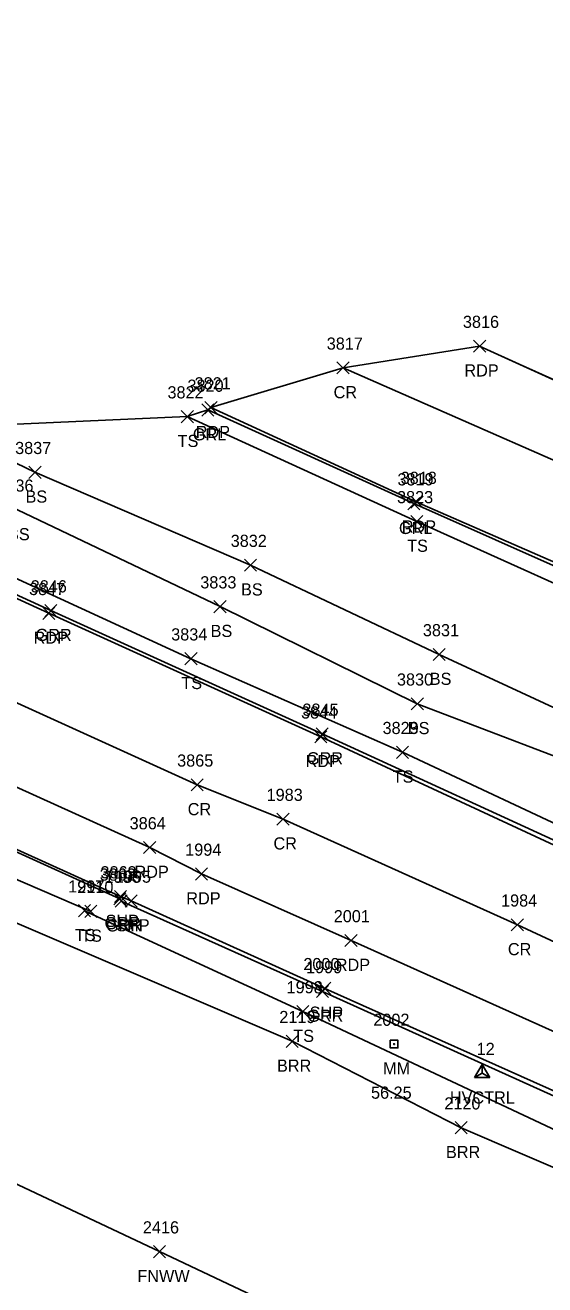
# Model space of a CAD drawing. Extents: x 1599569 to 1610055, y 642560 to 647860.
# Drawn here: x 1601302.9 to 1601388.5, y 647279.1 to 647486.4 of the extents above; entities that cross this region are included whole.
import ezdxf

# ---------------------------------------------------------------- set-up
doc = ezdxf.new("R2010")
doc.units = 0
for name, color, linetype in [('C_A', 7, 'Continuous'), ('C_I', 7, 'Continuous'), ('CPSM', 7, 'Continuous'), ('L_A', 7, 'Continuous'), ('L_I', 7, 'Continuous'), ('L_TIC', 7, 'Continuous'), ('LABL', 7, 'Continuous'), ('LELB', 7, 'Continuous'), ('LFNC', 7, 'Continuous'), ('LSOGP', 7, 'Continuous'), ('P_A', 7, 'Continuous'), ('P_I', 7, 'Continuous'), ('P_TIC', 7, 'Continuous'), ('PET', 7, 'Continuous'), ('PRC', 7, 'Continuous'), ('PSP', 7, 'Continuous'), ('R_A', 7, 'Continuous'), ('R_I', 7, 'Continuous'), ('R_TIC', 7, 'Continuous'), ('RGR', 7, 'Continuous'), ('S_A', 7, 'Continuous'), ('S_C', 7, 'Continuous'), ('S_I', 7, 'Continuous'), ('SRM', 7, 'Continuous')]:
    doc.layers.add(name, color=color, linetype=linetype)

msp = doc.modelspace()

# ---------------------------------------------------------------- linework, layer by layer
at = {"layer": 'CPSM'}
for p, q in [((1601376.92, 647313.16), (1601378.17, 647315.33)), ((1601379.42, 647313.16), (1601378.17, 647315.33)), ((1601378.17, 647313.88), (1601378.17, 647315.33)), ((1601376.92, 647313.16), (1601378.17, 647313.88)), ((1601376.92, 647313.16), (1601379.42, 647313.16)), ((1601378.17, 647313.88), (1601378.17, 647313.88)), ((1601378.17, 647313.88), (1601379.42, 647313.16))]:
    msp.add_line(p, q, dxfattribs=at)
at = {"layer": 'L_TIC'}
for points in [[(1601328.63, 647420.95), (1601330.63, 647422.95)], [(1601330.63, 647420.95), (1601328.63, 647422.95)], [(1601303.55, 647411.79), (1601305.55, 647413.79)], [(1601305.55, 647411.79), (1601303.55, 647413.79)], [(1601366.42, 647403.7), (1601368.42, 647405.7)], [(1601368.42, 647403.7), (1601366.42, 647405.7)], [(1601339.04, 647396.51), (1601341.04, 647398.51)], [(1601341.04, 647396.51), (1601339.04, 647398.51)], [(1601334.03, 647389.68), (1601336.03, 647391.68)], [(1601336.03, 647389.68), (1601334.03, 647391.68)], [(1601370.11, 647381.8), (1601372.11, 647383.8)], [(1601372.11, 647381.8), (1601370.11, 647383.8)], [(1601329.24, 647381.11), (1601331.24, 647383.11)], [(1601331.24, 647381.11), (1601329.24, 647383.11)], [(1601366.5, 647373.69), (1601368.5, 647375.69)], [(1601368.5, 647373.69), (1601366.5, 647375.69)], [(1601364.05, 647365.71), (1601366.05, 647367.71)], [(1601366.05, 647365.71), (1601364.05, 647367.71)], [(1601311.72, 647339.63), (1601313.72, 647341.63)], [(1601313.72, 647339.63), (1601311.72, 647341.63)], [(1601312.74, 647339.53), (1601314.74, 647341.53)], [(1601314.74, 647339.53), (1601312.74, 647341.53)], [(1601347.67, 647323.04), (1601349.67, 647325.04)], [(1601349.67, 647323.04), (1601347.67, 647325.04)], [(1601345.91, 647318.14), (1601347.91, 647320.14)], [(1601347.91, 647318.14), (1601345.91, 647320.14)], [(1601373.73, 647303.92), (1601375.73, 647305.92)], [(1601375.73, 647303.92), (1601373.73, 647305.92)], [(1601324.07, 647283.52), (1601326.07, 647285.52)], [(1601326.07, 647283.52), (1601324.07, 647285.52)]]:
    msp.add_lwpolyline(points, dxfattribs=at)
at = {"layer": 'LABL'}
msp.add_lwpolyline([(1601168.99, 647399.27), (1601207.41, 647380.73), (1601257.17, 647358.28), (1601294.19, 647341.7), (1601346.91, 647319.14), (1601374.73, 647304.92), (1601415.9, 647287.21), (1601447.46, 647269.36), (1601451.82, 647260.74), (1601445.32, 647247.33), (1601438.38, 647230.38)], dxfattribs=at)
at = {"layer": 'LELB'}
for points in [[(1601329.63, 647421.95), (1601367.42, 647404.7), (1601406.64, 647387), (1601445.7, 647369.36)], [(1601401.43, 647361.74), (1601367.5, 647374.69), (1601335.03, 647390.68), (1601301.67, 647406.6), (1601272.46, 647419.68)], [(1601404.15, 647367.47), (1601371.11, 647382.8), (1601340.04, 647397.51), (1601304.55, 647412.79), (1601289.24, 647420.16)], [(1601397.61, 647351.48), (1601365.05, 647366.71), (1601330.24, 647382.11), (1601297.6, 647397.08), (1601270.69, 647410.14), (1601258.21, 647415.18)], [(1601313.74, 647340.53), (1601281.28, 647354.51), (1601244.25, 647370.69), (1601204.7, 647388.89), (1601171.96, 647403.26)], [(1601312.72, 647340.63), (1601348.67, 647324.04), (1601393.17, 647303.13), (1601430.32, 647286.54), (1601444.15, 647280.37), (1601455.78, 647274.35)]]:
    msp.add_lwpolyline(points, dxfattribs=at)
at = {"layer": 'LFNC'}
msp.add_lwpolyline([(1601438.38, 647230.38), (1601406.08, 647246.23), (1601390.36, 647253.65), (1601325.07, 647284.52), (1601295.93, 647298.24), (1601277.64, 647306.94), (1601251.54, 647319.32), (1601236.24, 647326.06), (1601200.38, 647343.03), (1601163.89, 647358.89), (1601138.18, 647369.81), (1601105.25, 647383.87), (1601061.33, 647402.55), (1601021.95, 647420.15), (1600970.86, 647443.1), (1600923.39, 647465.04), (1600876.08, 647486.37)], dxfattribs=at)
at = {"layer": 'LSOGP'}
msp.add_lwpolyline([(1601530.11, 647456.05), (1601510.54, 647444.31), (1601507.68, 647443.39), (1601494.87, 647440.15), (1601486.2, 647439.92), (1601474.51, 647437.13), (1601463.02, 647434.13), (1601426.77, 647435.66), (1601423.36, 647434.8), (1601419.4, 647433.66), (1601410.55, 647433.57), (1601408.62, 647430.82), (1601390.73, 647427.66), (1601384.25, 647430.6), (1601377.76, 647433.55), (1601355.28, 647429.97), (1601333.53, 647423.43), (1601333.01, 647423.04), (1601329.63, 647421.95), (1601289.24, 647420.17)], dxfattribs=at)
at = {"layer": 'P_TIC'}
for points in [[(1601376.76, 647432.55), (1601378.76, 647434.55)], [(1601378.76, 647432.55), (1601376.76, 647434.55)], [(1601354.28, 647428.97), (1601356.28, 647430.97)], [(1601356.28, 647428.97), (1601354.28, 647430.97)], [(1601332.53, 647422.43), (1601334.53, 647424.43)], [(1601334.53, 647422.43), (1601332.53, 647424.43)], [(1601366.45, 647406.87), (1601368.45, 647408.87)], [(1601368.45, 647406.87), (1601366.45, 647408.87)], [(1601305.84, 647388.58), (1601307.84, 647390.58)], [(1601307.84, 647388.58), (1601305.84, 647390.58)], [(1601350.62, 647368.26), (1601352.62, 647370.26)], [(1601352.62, 647368.26), (1601350.62, 647370.26)], [(1601330.27, 647360.35), (1601332.27, 647362.35)], [(1601332.27, 647360.35), (1601330.27, 647362.35)], [(1601344.39, 647354.71), (1601346.39, 647356.71)], [(1601346.39, 647354.71), (1601344.39, 647356.71)], [(1601322.45, 647350.03), (1601324.45, 647352.03)], [(1601324.45, 647350.03), (1601322.45, 647352.03)], [(1601330.98, 647345.68), (1601332.98, 647347.68)], [(1601332.98, 647345.68), (1601330.98, 647347.68)], [(1601317.65, 647341.96), (1601319.65, 647343.96)], [(1601319.65, 647341.96), (1601317.65, 647343.96)], [(1601319.4, 647341.24), (1601321.4, 647343.24)], [(1601321.4, 647341.24), (1601319.4, 647343.24)], [(1601382.98, 647337.31), (1601384.98, 647339.31)], [(1601384.98, 647337.31), (1601382.98, 647339.31)], [(1601355.59, 647334.73), (1601357.59, 647336.73)], [(1601357.59, 647334.73), (1601355.59, 647336.73)], [(1601351.25, 647326.85), (1601353.25, 647328.85)], [(1601353.25, 647326.85), (1601351.25, 647328.85)]]:
    msp.add_lwpolyline(points, dxfattribs=at)
at = {"layer": 'PET'}
for points in [[(1601456, 647398.34), (1601403.7, 647421.77), (1601377.76, 647433.55)], [(1601447.48, 647372.41), (1601407.15, 647390.53), (1601367.45, 647407.87), (1601333.53, 647423.43)], [(1601396.17, 647348.54), (1601351.62, 647369.26), (1601306.84, 647389.58), (1601254.97, 647413.31)], [(1601190.18, 647411.64), (1601227.12, 647394.53), (1601270.37, 647375.05), (1601323.45, 647351.03)], [(1601323.45, 647351.03), (1601331.98, 647346.68)], [(1601331.98, 647346.68), (1601356.59, 647335.73), (1601398.36, 647316.98), (1601437.48, 647298.89), (1601470.99, 647284.11), (1601510.02, 647266.15), (1601543.75, 647251.34), (1601580.52, 647234.21), (1601606.39, 647222.8), (1601650.31, 647202.92), (1601693.14, 647183.7), (1601742.76, 647160.97), (1601795.46, 647137.6), (1601852.51, 647112.19)]]:
    msp.add_lwpolyline(points, dxfattribs=at)
at = {"layer": 'PRC'}
for points in [[(1601451.16, 647387.17), (1601410.55, 647405.73), (1601355.28, 647429.97)], [(1601212.28, 647415.26), (1601242.6, 647401.76), (1601275.09, 647386.85), (1601331.27, 647361.35)], [(1601331.27, 647361.35), (1601345.39, 647355.71)], [(1601345.39, 647355.71), (1601383.98, 647338.31), (1601428.29, 647317.74), (1601472.83, 647297.09), (1601504.71, 647281.99), (1601534.71, 647269.01), (1601561.28, 647257.19), (1601605.65, 647237.34), (1601658.4, 647213.63), (1601702.28, 647194), (1601743.84, 647175.46), (1601792.12, 647154.22), (1601833.09, 647135.23), (1601874.76, 647116.71)]]:
    msp.add_lwpolyline(points, dxfattribs=at)
at = {"layer": 'PSP'}
for points in [[(1601176.24, 647407.45), (1601222.94, 647386.72), (1601266.29, 647366.67), (1601318.65, 647342.96)], [(1601318.65, 647342.96), (1601320.4, 647342.24)], [(1601320.4, 647342.24), (1601352.25, 647327.85), (1601395.49, 647308.51), (1601432.16, 647291.56), (1601467.04, 647275.92), (1601506.79, 647257.96), (1601540.92, 647242.41), (1601577, 647226.25), (1601607.65, 647212.12), (1601646.7, 647194.68), (1601690.56, 647174.95), (1601738.15, 647153.57), (1601769.56, 647138.92), (1601808.48, 647121.32)]]:
    msp.add_lwpolyline(points, dxfattribs=at)
at = {"layer": 'R_TIC'}
for points in [[(1601332.01, 647422.04), (1601334.01, 647424.04)], [(1601334.01, 647422.04), (1601332.01, 647424.04)], [(1601365.93, 647406.63), (1601367.93, 647408.63)], [(1601367.93, 647406.63), (1601365.93, 647408.63)], [(1601306.17, 647389.02), (1601308.17, 647391.02)], [(1601308.17, 647389.02), (1601306.17, 647391.02)], [(1601350.85, 647368.72), (1601352.85, 647370.72)], [(1601352.85, 647368.72), (1601350.85, 647370.72)], [(1601317.53, 647341.58), (1601319.53, 647343.58)], [(1601319.53, 647341.58), (1601317.53, 647343.58)], [(1601317.76, 647341.22), (1601319.76, 647343.22)], [(1601319.76, 647341.22), (1601317.76, 647343.22)], [(1601350.89, 647326.35), (1601352.89, 647328.35)], [(1601352.89, 647326.35), (1601350.89, 647328.35)]]:
    msp.add_lwpolyline(points, dxfattribs=at)
at = {"layer": 'RGR'}
for points in [[(1601447.19, 647371.67), (1601406.79, 647389.93), (1601366.93, 647407.63), (1601333.01, 647423.04)], [(1601396.58, 647349.23), (1601351.85, 647369.72), (1601307.17, 647390.02), (1601255.19, 647413.85)], [(1601176.1, 647407.2), (1601222.59, 647386.13), (1601266.22, 647366.28), (1601318.53, 647342.58)], [(1601318.76, 647342.22), (1601351.89, 647327.35), (1601395.14, 647307.81), (1601432.06, 647291.1), (1601467.03, 647275.18), (1601506.65, 647256.87), (1601540.97, 647241.89), (1601576.91, 647225.43), (1601607.45, 647211.71), (1601646.25, 647193.96), (1601690.44, 647174.37), (1601737.84, 647152.88), (1601768.28, 647138.94), (1601807.48, 647120.85)]]:
    msp.add_lwpolyline(points, dxfattribs=at)
at = {"layer": 'SRM'}
msp.add_lwpolyline([(1601363.05, 647319.31), (1601364.3, 647319.31), (1601364.3, 647318.06), (1601363.05, 647318.06)], close=True, dxfattribs=at)
msp.add_circle((1601363.68, 647318.69), 0.0833, dxfattribs=at)

# ---------------------------------------------------------------- texts
at = {"layer": 'C_A'}
msp.add_text('HVCTRL', height=2, dxfattribs=at).set_placement((1601372.86, 647308.89))
at = {"layer": 'C_I'}
msp.add_text('12', height=2, dxfattribs=at).set_placement((1601377.27, 647316.89))
at = {"layer": 'L_A'}
for s, p in [('TS', (1601328.04, 647416.95)), ('BS', (1601303, 647407.79)), ('BS', (1601300.12, 647401.6)), ('TS', (1601365.83, 647399.7)), ('BS', (1601338.48, 647392.51)), ('BS', (1601333.47, 647385.68)), ('BS', (1601369.55, 647377.8)), ('TS', (1601328.65, 647377.11)), ('BS', (1601365.94, 647369.69)), ('TS', (1601363.46, 647361.71)), ('TS', (1601311.13, 647335.63)), ('TS', (1601312.15, 647335.53)), ('TS', (1601347.08, 647319.04)), ('BRR', (1601344.4, 647314.14)), ('BRR', (1601372.22, 647299.92)), ('FNWW', (1601321.41, 647279.52))]:
    msp.add_text(s, height=2, dxfattribs=at).set_placement(p)
at = {"layer": 'L_I'}
for s, p in [('3822', (1601326.37, 647424.95)), ('3837', (1601301.29, 647415.79)), ('3836', (1601298.36, 647409.6)), ('3823', (1601364.16, 647407.7)), ('3832', (1601336.78, 647400.51)), ('3833', (1601331.77, 647393.68)), ('3831', (1601368.42, 647385.8)), ('3834', (1601326.98, 647385.11)), ('3830', (1601364.15, 647377.69)), ('3829', (1601361.78, 647369.71)), ('1997', (1601310.03, 647343.63)), ('2110', (1601311.52, 647343.53)), ('1998', (1601345.98, 647327.04)), ('2119', (1601344.78, 647322.14)), ('2120', (1601371.95, 647307.92)), ('2416', (1601322.32, 647287.52))]:
    msp.add_text(s, height=2, dxfattribs=at).set_placement(p)
at = {"layer": 'P_A'}
for s, p in [('RDP', (1601375.25, 647428.55)), ('CR', (1601353.72, 647424.97)), ('RDP', (1601331.02, 647418.43)), ('RDP', (1601364.94, 647402.87)), ('RDP', (1601304.33, 647384.58)), ('RDP', (1601349.11, 647364.26)), ('CR', (1601329.7, 647356.35)), ('CR', (1601343.82, 647350.71)), ('RDP', (1601320.94, 647346.03)), ('RDP', (1601329.47, 647341.68)), ('SHP', (1601316.18, 647337.96)), ('SHP', (1601317.93, 647337.24)), ('CR', (1601382.41, 647333.31)), ('RDP', (1601354.08, 647330.73)), ('SHP', (1601349.78, 647322.85))]:
    msp.add_text(s, height=2, dxfattribs=at).set_placement(p)
at = {"layer": 'P_I'}
for s, p in [('3816', (1601375.01, 647436.55)), ('3817', (1601352.59, 647432.97)), ('3821', (1601330.84, 647426.43)), ('3818', (1601364.76, 647410.87)), ('3847', (1601303.58, 647392.58)), ('3844', (1601348.36, 647372.26)), ('3865', (1601327.96, 647364.35)), ('1983', (1601342.69, 647358.71)), ('3864', (1601320.14, 647354.03)), ('1994', (1601329.29, 647349.68)), ('3863', (1601315.34, 647345.96)), ('1995', (1601317.71, 647345.24)), ('1984', (1601381.29, 647341.31)), ('2001', (1601353.74, 647338.73)), ('2000', (1601348.74, 647330.85))]:
    msp.add_text(s, height=2, dxfattribs=at).set_placement(p)
at = {"layer": 'R_A'}
for s, p in [('GRL', (1601330.55, 647418.04)), ('GRL', (1601364.48, 647402.63)), ('GRR', (1601304.66, 647385.02)), ('GRR', (1601349.33, 647364.72)), ('GRR', (1601316.01, 647337.58)), ('GRR', (1601316.25, 647337.22)), ('GRR', (1601349.38, 647322.35))]:
    msp.add_text(s, height=2, dxfattribs=at).set_placement(p)
at = {"layer": 'R_I'}
for s, p in [('3820', (1601329.66, 647426.04)), ('3819', (1601364.23, 647410.63)), ('3846', (1601303.86, 647393.02)), ('3845', (1601348.59, 647372.72)), ('3862', (1601315.22, 647345.58)), ('1996', (1601316.01, 647345.22)), ('1999', (1601349.19, 647330.35))]:
    msp.add_text(s, height=2, dxfattribs=at).set_placement(p)
at = {"layer": 'S_A'}
msp.add_text('MM', height=2, dxfattribs=at).set_placement((1601361.87, 647313.69))
at = {"layer": 'S_C'}
msp.add_text('56.25', height=2, dxfattribs=at).set_placement((1601359.88, 647309.69))
at = {"layer": 'S_I'}
msp.add_text('2002', height=2, dxfattribs=at).set_placement((1601360.26, 647321.69))

doc.saveas('drawing.dxf')
